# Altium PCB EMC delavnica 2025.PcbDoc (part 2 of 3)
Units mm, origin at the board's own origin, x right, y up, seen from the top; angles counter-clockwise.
Board outline 146.35 x 55.01 mm, 2 copper layers (Top Layer, Bottom Layer), stack 1.671 mm thick; 5 components, 5 nets, 32 pads, 0 vias.
Unrouted connection lines stored in the file: 7.
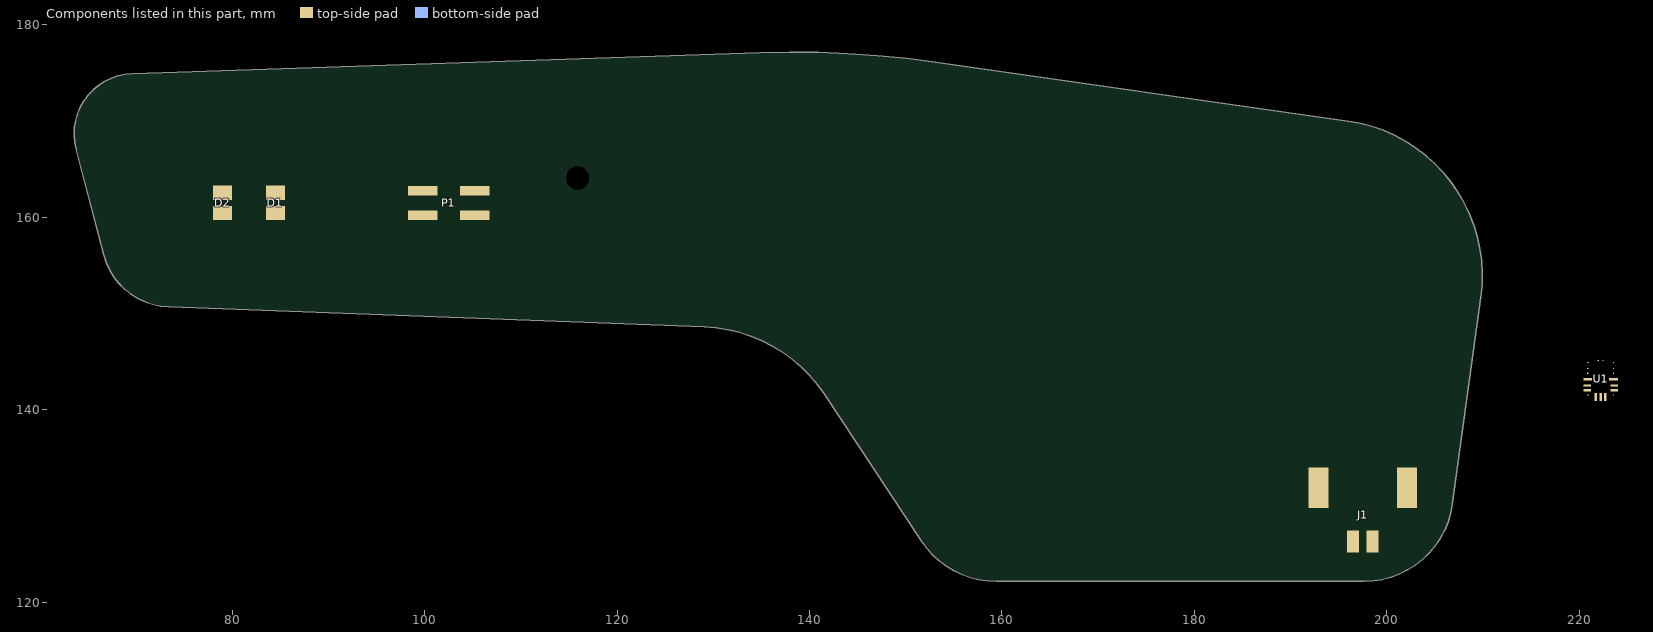
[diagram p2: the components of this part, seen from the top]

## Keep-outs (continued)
Top Layer: (continued)
  lines w0.203: 70.763,165.504 ccw(c71.252,166.272) 70.764,165.503 ; 74.51,166.422 cw(c73.659,166.748) 74.51,166.421 ; 121.556,166.282 121.788,166.242 ; 121.961,166.194 ccw(c121.633,165.344) 121.961,166.194 ; 122.178,166.11 cw(c121.852,165.259) 122.179,166.11 ; 123.096,162.363 ccw(c122.328,162.852) 123.097,162.364 ; 199.752,159.909 cw(c199.426,159.058) 199.753,159.909 ; 69.684,167.409 cw(c70.595,167.432) 69.697,167.587 ; 69.684,167.409 cw(c70.595,167.432) 69.697,167.587 ; 69.684,167.409 69.69,167.174 ; 69.69,167.174 ccw(c70.601,167.197) 69.712,166.996 ; 69.69,167.174 ccw(c70.601,167.197) 69.712,166.996 ; 69.697,167.587 69.737,167.818 ; 69.712,166.996 69.763,166.767 ; 69.737,167.818 cw(c70.635,167.663) 69.784,167.991 ; 69.737,167.818 cw(c70.635,167.663) 69.784,167.991 ; 69.763,166.767 ccw(c70.652,166.967) 69.819,166.598 ; 69.763,166.767 ccw(c70.652,166.967) 69.819,166.598 ; 69.784,167.991 ccw(c70.209,167.827) 69.784,167.991 ; 69.784,167.991 cw(c70.209,167.827) 69.784,167.991 ; 69.784,167.991 cw(c70.635,167.663) 69.785,167.991 ; 69.784,167.991 cw(c70.21,167.828) 69.784,167.991 ; 69.784,167.991 69.785,167.992 ; 69.784,167.991 cw(c70.209,167.827) 69.785,167.992 ; 69.785,167.991 cw(c70.635,167.663) 69.785,167.992 ; 69.785,167.991 69.868,168.209 ; 69.784,167.991 69.785,167.991 ; 69.785,167.992 ccw(c70.635,167.663) 69.785,167.992 ; 69.819,166.598 69.915,166.383 ; 69.868,168.209 ccw(c70.719,167.883) 69.868,168.209 ; 69.868,168.209 ccw(c70.719,167.883) 69.868,168.209 ; 69.868,168.209 cw(c70.719,167.883) 69.869,168.21 ; 69.868,168.209 cw(c70.294,168.046) 69.869,168.21 ; 69.868,168.209 ccw(c70.294,168.046) 69.868,168.209 ; 69.868,168.209 cw(c70.294,168.046) 69.869,168.21 ; 69.868,168.209 69.869,168.21 ; 69.869,168.21 cw(c70.719,167.883) 69.949,168.369 ; 69.869,168.21 cw(c70.719,167.883) 69.949,168.369 ; 69.869,168.21 ccw(c70.294,168.046) 69.869,168.21 ; 69.915,166.383 ccw(c70.748,166.752) 70.003,166.227 ; 69.915,166.383 ccw(c70.748,166.752) 70.003,166.227 ; 69.949,168.369 70.074,168.568 ; 70.003,166.227 ccw(c70.375,166.49) 70.003,166.227 ; 70.003,166.227 ccw(c70.375,166.49) 70.003,166.227 ; 70.003,166.227 ccw(c70.375,166.49) 70.003,166.227 ; 70.003,166.227 ccw(c70.375,166.49) 70.003,166.227 ; 70.003,166.227 ccw(c70.375,166.49) 70.003,166.227 cw(c70.748,166.752) 70.003,166.227 ; 70.003,166.227 ccw(c70.375,166.49) 70.003,166.227 ; 70.003,166.227 ccw(c70.748,166.752) 70.003,166.227 ; 70.003,166.227 70.138,166.036 ; 70.003,166.227 70.003,166.227 ; 70.074,168.568 cw(c70.845,168.082) 70.184,168.709 ; 70.074,168.568 cw(c70.845,168.082) 70.184,168.709 ; 70.138,166.036 ccw(c70.51,166.298) 70.138,166.036 ; 70.137,166.036 ccw(c70.51,166.298) 70.138,166.036 ; 70.138,166.036 ccw(c70.511,166.298) 70.138,166.036 ; 70.137,166.036 ccw(c70.511,166.298) 70.138,166.036 ; 70.137,166.036 70.138,166.036 ; 70.138,166.036 ccw(c70.51,166.298) 70.138,166.036 ; 70.138,166.036 ccw(c70.511,166.298) 70.138,166.035 ccw(c70.883,166.56) 70.255,165.9 ; 70.138,166.036 ccw(c70.511,166.298) 70.138,166.036 ; 70.138,166.036 ccw(c70.511,166.298) 70.138,166.036 ; 70.138,166.036 ccw(c70.883,166.56) 70.255,165.9 ; 70.138,166.036 ccw(c70.883,166.56) 70.138,166.036 ; 70.184,168.71 cw(c70.515,168.396) 70.185,168.711 ; 70.184,168.709 ccw(c70.514,168.395) 70.184,168.709 ; 70.184,168.71 ccw(c70.514,168.395) 70.184,168.709 ; 70.184,168.71 ccw(c70.845,168.082) 70.184,168.709 ; 70.184,168.71 cw(c70.845,168.082) 70.185,168.71 ; 70.184,168.709 ccw(c70.845,168.082) 70.184,168.709 ; 70.184,168.709 ccw(c70.515,168.396) 70.184,168.709 ; 70.184,168.71 ccw(c70.515,168.396) 70.184,168.709 ; 70.184,168.71 cw(c70.515,168.396) 70.185,168.71 70.185,168.71 ; 70.184,168.709 70.184,168.71 ; 70.185,168.711 ccw(c70.845,168.082) 70.185,168.71 ; 70.185,168.711 70.344,168.878 ; 70.185,168.71 70.185,168.711 ; 70.256,165.899 cw(c70.57,166.229) 70.255,165.9 ; 70.256,165.899 70.256,165.899 ; 70.256,165.899 70.255,165.9 ; 70.255,165.9 ccw(c70.569,166.23) 70.256,165.899 ; 70.255,165.9 ccw(c70.569,166.23) 70.255,165.9 ; 70.255,165.9 ccw(c70.569,166.23) 70.255,165.9 ; 70.255,165.9 ccw(c70.883,166.56) 70.256,165.899 ; 70.255,165.9 70.256,165.899 ; 70.256,165.899 ccw(c70.883,166.56) 70.256,165.899 ; 70.256,165.899 ccw(c70.883,166.56) 70.256,165.899 ; 70.256,165.899 70.424,165.739 ; 70.345,168.878 ccw(c71.006,168.252) 70.344,168.878 ; 70.345,168.878 cw(c71.006,168.252) 70.345,168.879 ; 70.344,168.878 cw(c70.675,168.565) 70.345,168.879 ; 70.345,168.878 70.345,168.879 cw(c70.675,168.565) 70.345,168.879 ; 70.344,168.878 70.345,168.878 ; 70.345,168.879 cw(c70.675,168.565) 70.346,168.88 ; 70.346,168.88 cw(c71.006,168.252) 70.346,168.88 ; 70.345,168.879 cw(c71.006,168.252) 70.346,168.88 ; 70.346,168.88 ccw(c70.676,168.566) 70.345,168.879 ; 70.345,168.879 70.346,168.88 ; 70.346,168.88 cw(c71.006,168.252) 70.481,168.996 ; 70.346,168.88 cw(c71.006,168.252) 70.481,168.996 ; 70.425,165.739 ccw(c70.739,166.068) 70.425,165.738 ; 70.424,165.739 ccw(c70.739,166.068) 70.425,165.739 ; 70.424,165.739 ccw(c70.738,166.069) 70.425,165.739 ; 70.424,165.739 cw(c70.738,166.069) 70.424,165.74 ccw(c71.053,166.398) 70.424,165.739 ; 70.425,165.739 ccw(c70.738,166.069) 70.425,165.738 ; 70.424,165.739 ccw(c70.738,166.069) 70.425,165.739 ; 70.425,165.739 ccw(c71.053,166.398) 70.425,165.738 ; 70.424,165.739 ccw(c71.053,166.398) 70.425,165.739 ; 70.425,165.739 70.425,165.738 ; 70.425,165.738 ccw(c71.053,166.398) 70.566,165.628 ; 70.425,165.738 ccw(c71.053,166.398) 70.425,165.738 ; 70.425,165.738 ccw(c71.053,166.398) 70.566,165.628 ; 70.481,168.996 70.673,169.132 ; 70.567,165.628 ccw(c70.81,166.013) 70.567,165.628 ; 70.566,165.628 ccw(c70.81,166.013) 70.567,165.628 ; 70.566,165.628 ccw(c70.81,166.013) 70.566,165.628 ; 70.567,165.628 ccw(c70.81,166.013) 70.567,165.628 ; 70.566,165.628 ccw(c70.81,166.013) 70.567,165.628 ; 70.566,165.628 ccw(c70.81,166.013) 70.566,165.628 ; 70.567,165.628 ccw(c70.81,166.013) 70.568,165.627 cw(c71.053,166.398) 70.567,165.628 ; 70.567,165.628 ccw(c70.81,166.013) 70.567,165.628 ; 70.567,165.628 ccw(c71.053,166.398) 70.567,165.628 ; 70.566,165.628 ccw(c71.053,166.398) 70.567,165.628 ; 70.566,165.628 ccw(c71.053,166.398) 70.566,165.628 ; 70.566,165.628 70.567,165.628 ; 70.567,165.628 70.764,165.503 ; 70.673,169.132 cw(c71.199,168.388) 70.828,169.22 ; 70.673,169.132 cw(c71.199,168.388) 70.828,169.22 ; 70.764,165.503 ccw(c71.008,165.887) 70.764,165.503 ; 70.764,165.503 ccw(c71.008,165.887) 70.764,165.503 ; 70.764,165.503 ccw(c71.007,165.888) 70.764,165.503 ; 70.764,165.503 ccw(c71.252,166.272) 70.764,165.503 ; 70.764,165.503 70.764,165.503 ; 70.764,165.503 ccw(c71.008,165.887) 70.765,165.503 ; 70.764,165.503 ccw(c71.008,165.887) 70.764,165.503 ; 70.764,165.503 ccw(c71.007,165.888) 70.764,165.503 ; 70.765,165.503 ccw(c71.252,166.272) 70.924,165.422 ; 70.764,165.503 ccw(c71.252,166.272) 70.924,165.422 ; 70.828,169.22 cw(c71.013,168.804) 70.829,169.22 ; 70.828,169.22 cw(c71.014,168.804) 70.829,169.22 ; 70.828,169.22 cw(c71.199,168.388) 70.829,169.22 ; 70.828,169.22 ccw(c71.199,168.388) 70.828,169.22 ; 70.828,169.22 70.829,169.22 ; 70.829,169.22 cw(c71.014,168.804) 70.829,169.221 ; 70.829,169.22 cw(c71.013,168.804) 70.829,169.221 ; 70.829,169.22 cw(c71.014,168.804) 70.829,169.221 ; 70.829,169.22 ccw(c71.199,168.388) 70.829,169.22 ; 70.829,169.22 cw(c71.199,168.388) 70.83,169.221 ccw(c71.014,168.804) 70.829,169.221 ; 70.829,169.22 70.829,169.221 ; 70.829,169.221 71.042,169.315 ; 70.924,165.422 71.143,165.338 ; 71.041,169.315 ccw(c71.413,168.483) 71.041,169.315 ; 71.041,169.315 cw(c71.413,168.483) 71.042,169.315 ; 71.042,169.315 ccw(c71.228,168.899) 71.041,169.315 ; 71.042,169.315 cw(c71.228,168.899) 71.042,169.315 ; 71.042,169.315 71.042,169.315 ; 71.041,169.315 71.042,169.315 ; 71.042,169.315 71.042,169.315 ; 71.042,169.315 71.042,169.315 ; 71.042,169.315 ccw(c71.227,168.899) 71.042,169.315 ; 71.043,169.316 cw(c71.413,168.483) 71.213,169.372 ; 71.042,169.315 cw(c71.413,168.483) 71.212,169.372 ; 71.043,169.316 ccw(c71.228,168.899) 71.042,169.315 ; 71.143,165.338 ccw(c71.471,166.188) 71.315,165.29 ; 71.143,165.338 ccw(c71.471,166.188) 71.315,165.29 ; 71.213,169.372 ccw(c71.313,168.928) 71.212,169.372 ; 71.213,169.372 ccw(c71.313,168.928) 71.213,169.372 ; 71.213,169.372 ccw(c71.313,168.928) 71.213,169.372 ; 71.213,169.372 cw(c71.313,168.928) 71.213,169.372 ; 71.213,169.372 cw(c71.413,168.483) 71.213,169.372 ; 71.213,169.372 ccw(c71.314,168.928) 71.213,169.372 ; 71.213,169.372 ccw(c71.314,168.928) 71.213,169.372 ; 71.213,169.372 71.214,169.372 ; 71.213,169.372 71.213,169.372 ; 71.213,169.372 71.213,169.372 ; 71.214,169.372 ccw(c71.314,168.928) 71.213,169.372 ; 71.214,169.372 ccw(c71.413,168.483) 71.213,169.372 ; 71.214,169.372 71.44,169.423 ; 71.315,165.29 ccw(c71.394,165.739) 71.315,165.29 ; 71.315,165.29 ccw(c71.471,166.188) 71.315,165.29 ; 71.315,165.29 ccw(c71.471,166.188) 71.315,165.29 ; 71.315,165.29 71.315,165.29 ; 71.315,165.29 ccw(c71.394,165.739) 71.316,165.29 ; 71.315,165.29 ccw(c71.393,165.739) 71.316,165.29 ; 71.315,165.29 ccw(c71.394,165.739) 71.317,165.29 ; 71.316,165.29 ccw(c71.471,166.188) 71.317,165.29 ; 71.315,165.29 ccw(c71.471,166.188) 71.316,165.29 ; 71.315,165.29 ccw(c71.471,166.188) 71.315,165.29 ; 71.316,165.29 71.317,165.29 ; 71.316,165.29 71.316,165.29 ; 71.317,165.29 ccw(c71.394,165.739) 71.317,165.29 ; 71.317,165.29 ccw(c71.394,165.739) 71.317,165.29 ; 71.317,165.29 71.546,165.25 ; 71.44,169.423 cw(c71.643,168.535) 71.441,169.424 ; 71.44,169.423 cw(c71.541,168.979) 71.441,169.424 ; 71.44,169.423 71.441,169.424 ; 71.44,169.423 71.44,169.423 ; 71.441,169.424 cw(c71.643,168.535) 71.442,169.424 ; 71.441,169.424 cw(c71.541,168.979) 71.441,169.424 ; 71.441,169.424 cw(c71.542,168.979) 71.441,169.424 ; 71.441,169.424 71.442,169.424 ; 71.441,169.424 71.441,169.424 ; 71.442,169.424 cw(c71.643,168.535) 71.619,169.446 ; 71.442,169.424 cw(c71.643,168.535) 71.619,169.446 ; 71.442,169.424 ccw(c71.541,168.979) 71.441,169.424 ; 71.442,169.424 ccw(c71.542,168.979) 71.441,169.424 ; 71.546,165.25 ccw(c71.703,166.148) 71.547,165.25 ; 71.546,165.25 ccw(c71.703,166.148) 71.546,165.25 ; 71.546,165.25 ccw(c71.625,165.699) 71.547,165.25 ; 71.546,165.25 ccw(c71.625,165.699) 71.546,165.25 ; 71.546,165.25 ccw(c71.624,165.699) 71.546,165.25 ; 71.546,165.25 ccw(c71.624,165.699) 71.546,165.25 ; 71.546,165.25 71.547,165.25 ; 71.546,165.25 71.546,165.25 ; 71.546,165.25 71.546,165.25 ; 71.546,165.25 ccw(c71.624,165.699) 71.547,165.25 ; 71.547,165.25 ccw(c71.703,166.148) 71.637,165.239 ; 71.547,165.25 ccw(c71.703,166.148) 71.637,165.239 ; 71.547,165.25 ccw(c71.625,165.699) 71.547,165.25 ; 71.619,169.446 cw(c71.643,168.535) 71.62,169.446 ; 71.619,169.446 ccw(c71.631,168.99) 71.619,169.446 ; 71.619,169.446 cw(c71.631,168.99) 71.62,169.446 ; 71.62,169.446 ccw(c71.631,168.991) 71.619,169.446 ; 71.62,169.446 71.62,169.446 ; 71.62,169.446 71.62,169.446 ; 71.62,169.446 71.62,169.446 ; 71.619,169.446 71.62,169.446 ; 71.62,169.446 ccw(c71.631,168.991) 71.62,169.446 ; 71.62,169.446 ccw(c71.643,168.535) 71.62,169.446 ; 71.62,169.446 ccw(c71.631,168.99) 71.62,169.446 ; 71.62,169.446 71.852,169.452 ; 71.62,169.446 71.62,169.446 ; 71.637,165.239 72.434,165.181 ; 71.853,169.452 ccw(c71.878,168.541) 71.852,169.452 cw(c71.865,168.997) 71.852,169.452 ; 71.853,169.452 cw(c71.878,168.541) 71.853,169.452 ; 71.853,169.452 cw(c71.865,168.997) 71.853,169.452 ; 71.853,169.452 cw(c71.866,168.997) 71.853,169.452 ; 71.852,169.452 cw(c71.865,168.997) 71.853,169.452 ; 71.853,169.452 71.853,169.452 ; 71.852,169.452 71.853,169.452 ; 71.854,169.452 ccw(c71.878,168.541) 71.854,169.452 ; 71.854,169.452 cw(c71.878,168.541) 71.944,169.45 ; 71.854,169.452 ccw(c71.878,168.541) 71.853,169.452 ; 71.854,169.452 cw(c71.878,168.541) 71.944,169.45 ; 71.854,169.452 ccw(c71.865,168.997) 71.853,169.452 ; 71.854,169.452 ccw(c71.866,168.997) 71.853,169.452 ; 71.853,169.452 71.854,169.452 ; 71.944,169.45 72.742,169.392 ; 72.434,165.181 ccw(c72.501,166.089) 72.525,165.178 ; 72.434,165.181 ccw(c72.501,166.089) 72.525,165.178 ; 72.525,165.178 ccw(c72.513,165.634) 72.526,165.178 ; 72.525,165.178 ccw(c72.513,165.634) 72.525,165.178 ; 72.525,165.178 ccw(c72.501,166.089) 72.526,165.178 ; 72.525,165.178 ccw(c72.514,165.634) 72.526,165.178 ; 72.525,165.178 ccw(c72.514,165.634) 72.525,165.178 ; 72.525,165.178 72.526,165.178 ; 72.526,165.178 ccw(c72.514,165.634) 72.527,165.179 ; 72.526,165.178 ccw(c72.501,166.089) 72.527,165.179 ; 72.526,165.178 72.527,165.179 ; 72.526,165.178 72.526,165.178 ; 72.527,165.179 72.758,165.185 ; 72.527,165.179 72.527,165.179 ; 72.742,169.392 cw(c72.676,168.483) 72.831,169.381 ; 72.742,169.392 cw(c72.676,168.483) 72.831,169.381 ; 72.758,165.185 ccw(c72.736,166.095) 72.759,165.185 ; 72.758,165.185 ccw(c72.736,166.095) 72.758,165.185 ; 72.758,165.185 ccw(c72.747,165.64) 72.759,165.185 ; 72.758,165.185 72.759,165.185 ; 72.758,165.185 72.758,165.185 ; 72.759,165.185 ccw(c72.748,165.64) 72.759,165.185 ; 72.759,165.185 ccw(c72.747,165.64) 72.759,165.185 ; 72.759,165.185 ccw(c72.747,165.64) 72.759,165.185 ; 72.759,165.185 ccw(c72.736,166.095) 72.76,165.185 ; 72.759,165.185 72.76,165.185 ; 72.759,165.185 72.759,165.185 ; 72.759,165.185 ccw(c72.748,165.64) 72.76,165.185 ; 72.759,165.185 ccw(c72.747,165.64) 72.76,165.185 ; 72.76,165.185 ccw(c72.736,166.095) 72.937,165.207 ; 72.76,165.185 ccw(c72.736,166.095) 72.937,165.207 ; 72.76,165.185 ccw(c72.736,166.095) 72.76,165.185 ; 72.831,169.381 73.063,169.34 ; 72.937,165.207 73.166,165.259 ; 73.063,169.34 cw(c72.907,168.443) 73.235,169.293 ; 73.063,169.34 cw(c72.907,168.443) 73.235,169.293 ; 73.166,165.259 ccw(c72.965,166.147) 73.335,165.315 ; 73.166,165.259 ccw(c72.965,166.147) 73.335,165.315 ; 73.235,169.293 cw(c72.907,168.443) 73.236,169.293 ; 73.235,169.293 ccw(c72.907,168.443) 73.235,169.293 ; 73.235,169.293 cw(c73.071,168.868) 73.236,169.293 ; 73.235,169.293 cw(c73.072,168.867) 73.236,169.293 ; 73.235,169.293 73.236,169.293 ; 73.236,169.293 cw(c72.907,168.443) 73.237,169.292 ; 73.236,169.293 cw(c73.072,168.867) 73.237,169.292 ; 73.236,169.292 ccw(c73.072,168.867) 73.236,169.293 ; 73.236,169.292 73.237,169.292 ; 73.237,169.292 ccw(c72.907,168.443) 73.237,169.292 ; 73.237,169.292 ccw(c73.072,168.867) 73.237,169.292 ; 73.237,169.292 73.453,169.209 ; 73.237,169.292 73.237,169.292 ; 73.335,165.315 ccw(c73.151,165.731) 73.336,165.315 ; 73.335,165.315 ccw(c72.965,166.147) 73.336,165.315 ; 73.335,165.315 ccw(c72.965,166.147) 73.336,165.315 ; 73.335,165.315 73.336,165.315 ; 73.336,165.315 ccw(c73.151,165.731) 73.336,165.315 ; 73.336,165.315 ccw(c73.151,165.731) 73.337,165.315 cw(c72.965,166.147) 73.336,165.315 ; 73.336,165.315 ccw(c73.151,165.731) 73.336,165.315 ; 73.336,165.315 ccw(c73.15,165.731) 73.336,165.315 ; 73.336,165.315 ccw(c72.965,166.147) 73.336,165.315 ; 73.336,165.315 73.55,165.41 ; 73.453,169.209 ccw(c73.126,168.358) 73.452,169.209 ; 73.453,169.209 ccw(c73.126,168.358) 73.453,169.209 ; 73.453,169.209 cw(c73.126,168.358) 73.454,169.208 ; 73.453,169.209 cw(c73.289,168.784) 73.454,169.208 ; 73.453,169.209 ccw(c73.289,168.784) 73.453,169.209 ; 73.453,169.209 cw(c73.29,168.783) 73.454,169.208 ; 73.453,169.209 73.453,169.209 ; 73.453,169.209 73.453,169.209 ; 73.453,169.209 73.454,169.208 ; 73.454,169.208 cw(c73.126,168.358) 73.614,169.128 ; 73.454,169.208 cw(c73.126,168.358) 73.614,169.128 ; 73.454,169.208 ccw(c73.29,168.783) 73.454,169.208 ; 73.55,165.41 ccw(c73.365,165.826) 73.551,165.411 ; 73.55,165.41 ccw(c73.365,165.826) 73.55,165.41 ; 73.55,165.41 ccw(c73.365,165.827) 73.55,165.41 ; 73.55,165.41 ccw(c73.365,165.827) 73.55,165.41 ; 73.55,165.41 ccw(c73.365,165.826) 73.55,165.41 ; 73.549,165.41 ccw(c73.365,165.826) 73.55,165.41 ; 73.55,165.41 ccw(c73.18,166.243) 73.551,165.411 ; 73.55,165.41 ccw(c73.18,166.243) 73.55,165.41 ; 73.549,165.41 ccw(c73.18,166.243) 73.55,165.41 ; 73.55,165.41 73.551,165.411 ; 73.551,165.411 ccw(c73.18,166.243) 73.706,165.499 ; 73.55,165.41 ccw(c73.18,166.243) 73.551,165.411 ; 73.551,165.411 ccw(c73.18,166.243) 73.706,165.499 ; 73.614,169.128 73.813,169.002 ; 73.706,165.499 73.898,165.634 ; 73.813,169.002 cw(c73.325,168.232) 73.953,168.892 ; 73.813,169.002 cw(c73.325,168.232) 73.953,168.892 ; 73.898,165.634 ccw(c73.372,166.379) 74.032,165.751 ; 73.898,165.634 ccw(c73.372,166.379) 74.032,165.751 ; 73.953,168.892 74.124,168.73 ; 74.032,165.751 ccw(c73.372,166.379) 74.033,165.752 ; 74.032,165.751 ccw(c73.372,166.379) 74.033,165.751 ccw(c73.702,166.065) 74.033,165.752 ; 74.032,165.751 ccw(c73.703,166.066) 74.033,165.752 ; 74.032,165.751 74.033,165.752 ; 74.033,165.752 ccw(c73.703,166.066) 74.034,165.753 ; 74.033,165.752 ccw(c73.372,166.379) 74.034,165.752 ; 74.033,165.752 ccw(c73.703,166.066) 74.033,165.752 ; 74.033,165.752 74.034,165.752 ; 74.034,165.752 ccw(c73.372,166.379) 74.034,165.753 ; 74.034,165.752 74.034,165.753 ; 74.034,165.753 74.193,165.92 ; 74.124,168.73 cw(c73.495,168.07) 74.24,168.595 ; 74.124,168.73 cw(c73.495,168.07) 74.24,168.595 ; 74.194,165.921 ccw(c73.863,166.234) 74.194,165.921 ; 74.193,165.92 ccw(c73.534,166.549) 74.194,165.921 ; 74.193,165.92 ccw(c73.534,166.549) 74.193,165.92 ; 74.193,165.92 ccw(c73.863,166.234) 74.194,165.921 ; 74.193,165.92 74.194,165.921 ; 74.193,165.92 74.193,165.92 ; 74.194,165.921 ccw(c73.863,166.234) 74.194,165.921 ; 74.194,165.921 ccw(c73.534,166.549) 74.195,165.922 ; 74.194,165.921 ccw(c73.864,166.235) 74.194,165.921 ; 74.194,165.921 74.195,165.922 ; 74.195,165.922 ccw(c73.534,166.549) 74.304,166.062 ; 74.195,165.921 ccw(c73.534,166.549) 74.195,165.922 ; 74.194,165.921 ccw(c73.863,166.234) 74.195,165.922 ; 74.195,165.922 ccw(c73.534,166.549) 74.304,166.062 ; 74.194,165.921 ccw(c73.864,166.235) 74.195,165.921 ; 74.241,168.594 ccw(c73.495,168.07) 74.241,168.595 ; 74.241,168.594 ccw(c73.495,168.07) 74.241,168.594 ; 74.241,168.594 ccw(c73.868,168.332) 74.241,168.595 ; 74.241,168.594 74.241,168.595 ; 74.241,168.594 74.241,168.594 ; 74.241,168.594 74.375,168.404 ; 74.24,168.595 ccw(c73.495,168.07) 74.24,168.595 ; 74.241,168.595 ccw(c73.495,168.07) 74.24,168.595 ; 74.241,168.595 ccw(c73.868,168.333) 74.24,168.595 ; 74.241,168.595 ccw(c73.868,168.332) 74.24,168.595 ; 74.241,168.595 ccw(c73.868,168.332) 74.241,168.595 ; 74.24,168.595 74.241,168.595 ; 74.241,168.595 74.241,168.595 ; 74.304,166.062 74.43,166.261 ; 74.376,168.403 ccw(c74.003,168.141) 74.375,168.404 ; 74.376,168.403 cw(c74.003,168.141) 74.376,168.403 ; 74.375,168.403 ccw(c73.631,167.878) 74.375,168.404 ; 74.376,168.403 ccw(c73.631,167.878) 74.375,168.403 ; 74.376,168.403 cw(c73.631,167.878) 74.376,168.403 ; 74.376,168.403 ccw(c74.003,168.141) 74.375,168.404 ; 74.376,168.403 cw(c74.003,168.141) 74.376,168.403 ; 74.376,168.403 ccw(c74.003,168.141) 74.375,168.404 ; 74.376,168.403 74.376,168.403 ; 74.375,168.404 74.375,168.404 ; 74.375,168.404 74.375,168.403 ; 74.376,168.403 cw(c73.631,167.878) 74.464,168.248 ; 74.376,168.403 ccw(c73.631,167.878) 74.376,168.403 ; 74.376,168.403 cw(c73.631,167.878) 74.464,168.248 ; 74.43,166.261 ccw(c73.659,166.748) 74.51,166.421 ; 74.43,166.261 ccw(c73.659,166.748) 74.51,166.421 ; 74.464,168.248 74.559,168.033 ; 74.51,166.421 ccw(c74.085,166.585) 74.51,166.421 ; 74.51,166.421 ccw(c74.085,166.584) 74.51,166.421 ; 74.51,166.421 ccw(c74.085,166.584) 74.51,166.421 ; 74.51,166.421 ccw(c74.085,166.584) 74.51,166.421 ; 74.51,166.421 ccw(c73.659,166.748) 74.51,166.421 ; 74.51,166.421 ccw(c73.659,166.748) 74.51,166.421 ; 74.51,166.421 74.594,166.639 ; 74.51,166.421 74.51,166.421 ; 74.559,168.033 cw(c73.726,167.663) 74.615,167.863 ; 74.559,168.033 cw(c73.726,167.663) 74.615,167.863 ; 74.594,166.64 ccw(c73.744,166.967) 74.642,166.812 ; 74.594,166.639 ccw(c73.744,166.967) 74.594,166.64 ; 74.594,166.639 ccw(c73.744,166.967) 74.594,166.639 ; 74.594,166.639 ccw(c73.744,166.967) 74.594,166.639 ; 74.594,166.639 ccw(c74.169,166.803) 74.594,166.64 ; 74.594,166.64 ccw(c74.169,166.804) 74.594,166.64 ccw(c73.744,166.967) 74.642,166.812 ; 74.594,166.639 ccw(c74.169,166.804) 74.594,166.64 ; 74.594,166.639 ccw(c74.169,166.804) 74.594,166.639 ; 74.594,166.639 74.594,166.64 ; 74.594,166.639 74.594,166.639 ; 74.615,167.863 74.667,167.634 ; 74.642,166.812 74.682,167.044 ; 74.667,167.634 cw(c73.778,167.434) 74.689,167.457 ; 74.667,167.634 cw(c73.778,167.434) 74.689,167.457 ; 74.682,167.044 ccw(c73.784,167.199) 74.695,167.199 ; 74.682,167.044 ccw(c73.784,167.199) 74.695,167.199 ; 74.689,167.457 74.695,167.222 ; 74.695,167.199 ccw(c73.784,167.199) 74.695,167.222 ; 74.695,167.199 ccw(c73.784,167.199) 74.695,167.222 ; 119.148,163.453 ccw(c119.603,163.465) 119.148,163.452 ; 119.148,163.452 ccw(c119.603,163.465) 119.148,163.452 cw(c120.059,163.478) 119.148,163.453 ; 119.148,163.453 cw(c119.603,163.466) 119.148,163.454 ; 119.148,163.453 ccw(c119.603,163.466) 119.148,163.453 ; 119.148,163.453 cw(c119.603,163.465) 119.148,163.454 ; 119.148,163.453 ccw(c119.603,163.465) 119.148,163.453 ; 119.148,163.453 cw(c120.059,163.478) 119.148,163.454 ; 119.148,163.453 ccw(c120.059,163.478) 119.148,163.453 ; 119.148,163.452 119.154,163.22 ; 119.148,163.453 119.148,163.452 ; 119.148,163.453 119.148,163.453 ; 119.148,163.453 119.148,163.454 ; 119.148,163.454 cw(c120.059,163.478) 119.15,163.544 ; 119.148,163.454 cw(c120.059,163.478) 119.15,163.544 ; 119.148,163.454 ccw(c120.059,163.478) 119.148,163.454 ; 119.15,163.544 119.208,164.342 ; 119.154,163.22 ccw(c119.609,163.231) 119.154,163.219 ; 119.154,163.219 cw(c119.61,163.231) 119.154,163.22 ; 119.154,163.219 ccw(c119.61,163.231) 119.154,163.219 ; 119.154,163.219 ccw(c120.065,163.243) 119.176,163.042 ; 119.154,163.219 cw(c120.065,163.243) 119.154,163.22 ; 119.154,163.219 ccw(c120.065,163.243) 119.176,163.042 ; 119.154,163.22 119.154,163.219 ; 119.154,163.22 119.154,163.22 ; 119.154,163.22 119.154,163.22 ; 119.154,163.22 119.154,163.22 ; 119.154,163.22 ccw(c119.61,163.231) 119.154,163.22 ; 119.154,163.22 ccw(c120.065,163.243) 119.154,163.22 ; 119.154,163.22 ccw(c119.609,163.231) 119.154,163.22 ; 119.154,163.22 119.154,163.22 ; 119.177,163.04 cw(c119.621,163.141) 119.176,163.041 ; 119.177,163.04 cw(c120.065,163.243) 119.176,163.041 ; 119.177,163.04 119.228,162.814 ; 119.177,163.04 119.177,163.04 ; 119.177,163.04 119.176,163.041 ; 119.176,163.042 ccw(c119.621,163.142) 119.176,163.041 ; 119.176,163.041 ccw(c119.621,163.142) 119.176,163.041 ; 119.176,163.042 ccw(c119.621,163.141) 119.176,163.041 ; 119.176,163.041 ccw(c119.621,163.141) 119.176,163.041 ; 119.176,163.042 ccw(c120.065,163.243) 119.176,163.041 ; 119.176,163.041 119.176,163.041 ; 119.176,163.042 119.176,163.041 ; 119.208,164.342 cw(c120.117,164.276) 119.219,164.431 ; 119.208,164.342 cw(c120.117,164.276) 119.219,164.431 ; 119.219,164.431 119.26,164.663 ; 119.228,162.813 ccw(c119.672,162.914) 119.228,162.813 ; 119.228,162.813 ccw(c119.672,162.914) 119.228,162.813 ; 119.228,162.812 ccw(c120.117,163.013) 119.285,162.642 ; 119.228,162.813 cw(c120.117,163.013) 119.228,162.813 ; 119.228,162.813 ccw(c120.117,163.013) 119.284,162.643 ; 119.228,162.813 cw(c119.672,162.913) 119.228,162.813 ; 119.228,162.813 ccw(c119.672,162.913) 119.228,162.813 ; 119.228,162.813 ccw(c119.672,162.913) 119.228,162.813 ; 119.228,162.813 ccw(c119.672,162.913) 119.228,162.812 ; 119.228,162.813 119.228,162.813 ; 119.228,162.813 119.228,162.813 ; 119.228,162.813 119.228,162.814 ; 119.228,162.814 ccw(c120.117,163.013) 119.228,162.813 ; 119.228,162.814 ccw(c119.672,162.914) 119.228,162.813 ; 119.26,164.663 cw(c120.157,164.507) 119.307,164.835 ; 119.26,164.663 cw(c120.157,164.507) 119.307,164.835 ; 119.285,162.642 cw(c119.701,162.828) 119.285,162.642 ; 119.285,162.642 ccw(c119.701,162.828) 119.285,162.641 ; 119.285,162.641 cw(c120.117,163.013) 119.285,162.642 ; 119.285,162.641 ccw(c120.117,163.013) 119.285,162.641 ; 119.285,162.642 119.379,162.429 ; 119.285,162.642 119.285,162.642 ; 119.285,162.642 119.285,162.642 ; 119.285,162.642 119.285,162.641 ; 119.285,162.642 119.285,162.642 ; 119.284,162.643 ccw(c119.701,162.828) 119.285,162.642 ; 119.285,162.642 ccw(c119.701,162.827) 119.285,162.642 ; 119.307,164.835 cw(c119.733,164.672) 119.307,164.836 ; 119.307,164.835 cw(c119.732,164.671) 119.307,164.836 ; 119.307,164.835 ccw(c120.157,164.507) 119.307,164.835 ; 119.307,164.835 cw(c120.157,164.507) 119.307,164.836 ; 119.307,164.835 119.307,164.836 ; 119.308,164.836 ccw(c119.733,164.672) 119.307,164.836 ; 119.307,164.836 cw(c119.733,164.672) 119.308,164.837 ; 119.307,164.836 cw(c120.157,164.507) 119.308,164.837 ; 119.308,164.836 119.308,164.837 ; 119.308,164.837 ccw(c119.733,164.672) 119.308,164.837 ; 119.308,164.837 ccw(c120.157,164.507) 119.308,164.837 ; 119.308,164.837 119.308,164.837 ; 119.308,164.837 119.391,165.053 ; 119.38,162.428 ccw(c120.212,162.799) 119.38,162.428 ; 119.38,162.428 ccw(c120.212,162.799) 119.468,162.273 ; 119.38,162.428 cw(c120.212,162.799) 119.38,162.429 ; 119.38,162.428 ccw(c120.212,162.799) 119.468,162.273 ; 119.38,162.428 cw(c119.796,162.614) 119.38,162.429 ; 119.38,162.428 cw(c119.796,162.613) 119.38,162.429 ; 119.38,162.428 119.38,162.429 ; 119.38,162.429 cw(c120.212,162.799) 119.379,162.43 ccw(c119.796,162.614) 119.379,162.429 ; 119.38,162.429 ccw(c120.212,162.799) 119.38,162.429 ; 119.379,162.429 ccw(c119.796,162.614) 119.38,162.429 ; 119.379,162.429 ccw(c119.796,162.613) 119.38,162.429 ; 119.379,162.429 ccw(c119.796,162.614) 119.38,162.429 ; 119.379,162.429 119.38,162.429 ; 119.391,165.053 cw(c119.817,164.89) 119.392,165.054 ; 119.391,165.053 ccw(c119.816,164.889) 119.391,165.053 ; 119.391,165.053 cw(c119.816,164.889) 119.392,165.054 ; 119.391,165.053 cw(c120.242,164.726) 119.392,165.054 ; 119.391,165.053 ccw(c120.242,164.726) 119.391,165.053 ; 119.391,165.053 ccw(c120.242,164.726) 119.391,165.052 ; 119.391,165.053 119.392,165.054 ; 119.391,165.053 119.391,165.053 ; 119.391,165.053 119.391,165.053 ; 119.392,165.054 ccw(c119.817,164.89) 119.392,165.054 ; 119.392,165.054 cw(c120.242,164.726) 119.472,165.214 ; 119.392,165.054 cw(c120.242,164.726) 119.472,165.214 ; 119.468,162.273 119.604,162.081 ; 119.472,165.214 119.598,165.413 ; 119.598,165.413 cw(c120.368,164.925) 119.708,165.553 ; 119.598,165.413 cw(c120.368,164.925) 119.708,165.553 ; 119.604,162.081 ccw(c120.348,162.606) 119.72,161.946 ; 119.604,162.081 ccw(c120.348,162.606) 119.72,161.946 ; 119.708,165.553 119.87,165.724 ; 119.72,161.946 ccw(c120.348,162.606) 119.721,161.945 ; 119.72,161.946 ccw(c120.348,162.606) 119.72,161.946 ccw(c120.034,162.276) 119.721,161.945 ; 119.72,161.946 ccw(c120.035,162.275) 119.721,161.945 ; 119.72,161.946 119.721,161.945 ; 119.722,161.944 cw(c120.035,162.275) 119.721,161.945 ; 119.722,161.945 cw(c120.348,162.606) 119.721,161.945 ; 119.722,161.945 ccw(c120.348,162.606) 119.722,161.944 ; 119.722,161.944 119.889,161.785 ; 119.722,161.945 119.722,161.944 ; 119.722,161.945 119.721,161.945 ; 119.721,161.945 ccw(c120.035,162.275) 119.721,161.945 ; 119.87,165.724 cw(c120.53,165.095) 120.005,165.84 ; 119.87,165.724 cw(c120.53,165.095) 120.005,165.84 ; 119.889,161.785 ccw(c120.518,162.445) 119.89,161.785 ; 119.89,161.785 ccw(c120.518,162.445) 119.89,161.784 ; 119.889,161.785 ccw(c120.204,162.115) 119.89,161.784 ; 119.89,161.785 119.89,161.785 ; 119.889,161.785 119.89,161.785 ; 119.89,161.785 ccw(c120.204,162.115) 119.89,161.784 ; 119.89,161.784 ccw(c120.204,162.115) 119.891,161.784 ; 119.891,161.784 ccw(c120.204,162.115) 119.891,161.784 ; 119.891,161.784 ccw(c120.518,162.445) 119.891,161.784 ; 119.89,161.784 ccw(c120.518,162.445) 119.891,161.784 ; 119.89,161.784 ccw(c120.205,162.114) 119.891,161.784 ; 119.891,161.784 ccw(c120.205,162.114) 119.891,161.784 ; 119.89,161.784 119.891,161.784 ; 119.891,161.784 ccw(c120.518,162.445) 120.032,161.674 ; 119.891,161.784 ccw(c120.518,162.445) 120.032,161.674 ; 120.005,165.841 ccw(c120.268,165.468) 120.005,165.841 ; 120.005,165.841 ccw(c120.268,165.468) 120.005,165.84 ; 120.005,165.841 cw(c120.268,165.468) 120.006,165.841 ; 120.005,165.841 ccw(c120.267,165.468) 120.005,165.84 ; 120.005,165.841 cw(c120.53,165.095) 120.006,165.841 ; 120.005,165.841 ccw(c120.53,165.095) 120.005,165.84 ; 120.005,165.84 ccw(c120.53,165.095) 120.005,165.84 ; 120.005,165.841 120.006,165.841 ; 120.005,165.841 120.005,165.841 ; 120.005,165.84 120.005,165.841 ; 120.006,165.841 ccw(c120.53,165.095) 120.006,165.841 ; 120.006,165.841 120.196,165.975 ; 120.006,165.841 120.006,165.841 ; 120.032,161.674 120.231,161.549 ; 120.197,165.976 ccw(c120.459,165.603) 120.196,165.975 ; 120.197,165.976 cw(c120.459,165.603) 120.197,165.976 cw(c120.722,165.231) 120.197,165.976 ; 120.197,165.976 ccw(c120.459,165.603) 120.196,165.975 ; 120.197,165.976 cw(c120.722,165.231) 120.197,165.976 ; 120.197,165.976 ccw(c120.722,165.231) 120.197,165.975 ; 120.197,165.975 ccw(c120.722,165.231) 120.196,165.975 ; 120.197,165.976 cw(c120.459,165.603) 120.197,165.976 ; 120.197,165.976 ccw(c120.459,165.603) 120.196,165.975 ; 120.196,165.975 120.197,165.975 ; 120.196,165.975 120.196,165.975 ; 120.197,165.976 120.197,165.976 ; 120.197,165.976 cw(c120.722,165.231) 120.352,166.064 ; 120.197,165.976 cw(c120.722,165.231) 120.352,166.064 ; 120.231,161.549 ccw(c120.717,162.319) 120.39,161.469 ; 120.231,161.549 ccw(c120.717,162.319) 120.39,161.469 ; 120.352,166.064 120.567,166.159 ; 120.39,161.469 ccw(c120.554,161.894) 120.39,161.469 ; 120.39,161.469 ccw(c120.554,161.894) 120.391,161.468 ; 120.39,161.469 ccw(c120.554,161.894) 120.391,161.468 ; 120.39,161.469 ccw(c120.717,162.319) 120.391,161.468 ; 120.39,161.469 120.391,161.468 ; 120.391,161.468 ccw(c120.554,161.894) 120.391,161.468 ; 120.391,161.468 ccw(c120.717,162.319) 120.391,161.468 ; 120.391,161.468 ccw(c120.717,162.319) 120.391,161.468 ; 120.391,161.468 120.609,161.385 ; 120.567,166.159 cw(c120.937,165.326) 120.737,166.215 ; 120.567,166.159 cw(c120.937,165.326) 120.737,166.215 ; 120.609,161.385 cw(c120.937,162.235) 120.608,161.385 ; 120.609,161.385 ccw(c120.937,162.235) 120.609,161.384 ; 120.609,161.385 120.609,161.384 ; 120.608,161.385 ccw(c120.937,162.235) 120.608,161.385 ; 120.608,161.385 ccw(c120.773,161.809) 120.609,161.384 ; 120.608,161.385 120.609,161.384 ; 120.609,161.384 ccw(c120.772,161.81) 120.609,161.384 ; 120.609,161.384 ccw(c120.937,162.235) 120.782,161.337 ; 120.609,161.384 ccw(c120.937,162.235) 120.782,161.337 ; 120.609,161.384 ccw(c120.773,161.809) 120.609,161.384 ; 120.609,161.384 ccw(c120.773,161.809) 120.609,161.384 ; 120.737,166.215 120.966,166.267 ; 120.782,161.337 121.013,161.297 ; 120.966,166.267 cw(c121.166,165.378) 121.143,166.289 ; 120.966,166.267 cw(c121.166,165.378) 121.143,166.289 ; 121.013,161.297 ccw(c121.168,162.195) 121.191,161.284 ; 121.013,161.297 ccw(c121.168,162.195) 121.191,161.284 ; 121.143,166.289 121.378,166.295 ; 121.191,161.284 121.426,161.29 ; 121.378,166.295 cw(c121.401,165.384) 121.401,166.295 ; 121.378,166.295 cw(c121.401,165.384) 121.401,166.295 ; 121.401,166.295 cw(c121.401,165.384) 121.556,166.282 ccw(c121.401,165.384) 121.401,166.295 ; 121.426,161.29 ccw(c121.403,162.201) 121.604,161.312 ; 121.426,161.29 ccw(c121.403,162.201) 121.604,161.312 ; 121.604,161.312 121.833,161.363 ; 121.788,166.242 cw(c121.633,165.344) 121.96,166.194 cw(c121.796,165.769) 121.961,166.194 ; 121.788,166.242 cw(c121.633,165.344) 121.961,166.194 ; 121.833,161.363 ccw(c121.633,162.252) 122.002,161.419 ; 121.833,161.363 ccw(c121.633,162.252) 122.002,161.419 ; 121.961,166.194 ccw(c121.796,165.769) 121.961,166.194 ; 121.961,166.194 ccw(c121.796,165.769) 121.961,166.194 ; 121.961,166.194 ccw(c121.797,165.769) 121.961,166.194 ; 121.961,166.194 ccw(c121.633,165.344) 121.961,166.194 ; 121.961,166.194 ccw(c121.633,165.344) 121.961,166.194 ; 121.961,166.194 122.179,166.11 ; 121.961,166.194 121.961,166.194 ; 121.961,166.194 121.961,166.194 ; 122.002,161.419 122.217,161.515 ; 122.179,166.11 cw(c121.852,165.259) 122.339,166.03 ; 122.179,166.11 cw(c121.852,165.259) 122.339,166.03 ; 122.179,166.11 ccw(c121.852,165.259) 122.179,166.11 ; 122.179,166.11 ccw(c121.852,165.259) 122.179,166.11 ; 122.179,166.11 ccw(c122.016,165.685) 122.179,166.11 ; 122.179,166.11 ccw(c122.016,165.685) 122.179,166.11 ; 122.179,166.11 ccw(c122.016,165.685) 122.179,166.11 ; 122.179,166.11 ccw(c122.015,165.685) 122.179,166.11 ; 122.179,166.11 122.179,166.11 ; 122.217,161.515 ccw(c121.848,162.348) 122.373,161.603 ; 122.217,161.515 ccw(c121.848,162.348) 122.373,161.603 ; 122.339,166.03 122.538,165.904 ; 122.373,161.603 ccw(c121.848,162.348) 122.373,161.603 ; 122.373,161.603 ccw(c122.11,161.975) 122.373,161.603 ; 122.373,161.603 ccw(c122.11,161.975) 122.373,161.603 ; 122.373,161.603 122.373,161.603 ; 122.373,161.603 ccw(c121.848,162.348) 122.373,161.603 cw(c122.11,161.975) 122.373,161.603 ; 122.373,161.603 ccw(c122.11,161.975) 122.373,161.603 ; 122.373,161.603 ccw(c122.11,161.975) 122.373,161.603 ; 122.373,161.603 ccw(c122.11,161.975) 122.373,161.603 ; 122.373,161.603 122.564,161.738 ; 122.538,165.904 cw(c122.051,165.134) 122.678,165.795 ; 122.538,165.904 cw(c122.051,165.134) 122.678,165.795 ; 122.564,161.737 ccw(c122.302,162.111) 122.564,161.738 ; 122.564,161.738 ccw(c122.302,162.111) 122.564,161.738 ; 122.564,161.737 ccw(c122.302,162.11) 122.564,161.738 ; 122.564,161.738 ccw(c122.302,162.11) 122.564,161.738 ; 122.564,161.737 122.564,161.738 ; 122.564,161.738 ccw(c122.04,162.483) 122.564,161.738 ; 122.564,161.738 ccw(c122.04,162.483) 122.7,161.855 ; 122.564,161.738 ccw(c122.302,162.111) 122.564,161.738 ; 122.564,161.738 ccw(c122.302,162.111) 122.564,161.738 ; 122.564,161.738 ccw(c122.302,162.111) 122.565,161.738 ccw(c122.04,162.483) 122.7,161.855 ; 122.564,161.738 ccw(c122.302,162.11) 122.564,161.738 ; 122.679,165.794 cw(c122.365,165.464) 122.679,165.794 ; 122.679,165.794 ccw(c122.365,165.464) 122.679,165.795 ; 122.678,165.795 cw(c122.051,165.134) 122.679,165.794 ; 122.679,165.794 cw(c122.366,165.463) 122.679,165.794 ; 122.679,165.794 ccw(c122.366,165.463) 122.678,165.795 ; 122.679,165.795 ccw(c122.051,165.134) 122.678,165.795 ; 122.678,165.795 122.679,165.794 ; 122.68,165.793 ccw(c122.366,165.463) 122.679,165.794 ; 122.68,165.793 ccw(c122.051,165.134) 122.68,165.793 ; 122.68,165.793 ccw(c122.051,165.134) 122.679,165.794 ; 122.679,165.794 ccw(c122.366,165.463) 122.679,165.794 ; 122.68,165.793 122.847,165.634 ; 122.68,165.793 122.68,165.793 ; 122.679,165.794 122.68,165.793 ; 122.7,161.855 ccw(c122.04,162.483) 122.701,161.856 ; 122.7,161.855 ccw(c122.371,162.17) 122.701,161.856 ; 122.7,161.855 ccw(c122.37,162.169) 122.7,161.855 ; 122.7,161.855 ccw(c122.37,162.169) 122.7,161.855 ; 122.7,161.855 ccw(c122.37,162.169) 122.701,161.856 ; 122.7,161.855 122.701,161.856 ; 122.7,161.855 122.701,161.856 ; 122.701,161.856 122.701,161.856 ; 122.701,161.856 ccw(c122.04,162.483) 122.701,161.856 ; 122.701,161.856 ccw(c122.04,162.483) 122.701,161.856 ; 122.701,161.856 122.861,162.024 ; 122.848,165.634 cw(c122.221,164.972) 122.848,165.633 ; 122.848,165.634 ccw(c122.221,164.972) 122.847,165.634 ; 122.848,165.634 122.848,165.633 ; 122.848,165.634 122.847,165.634 ; 122.847,165.634 cw(c122.534,165.303) 122.848,165.633 ; 122.848,165.633 cw(c122.534,165.303) 122.849,165.632 ; 122.848,165.633 ccw(c122.534,165.303) 122.848,165.633 ; 122.848,165.633 cw(c122.221,164.972) 122.849,165.632 ; 122.848,165.633 cw(c122.535,165.302) 122.849,165.633 cw(c122.221,164.972) 122.849,165.632 ; 122.848,165.633 122.849,165.632 ; 122.849,165.632 cw(c122.221,164.972) 122.966,165.498 ; 122.849,165.632 cw(c122.221,164.972) 122.966,165.498 ; 122.861,162.024 cw(c122.202,162.653) 122.86,162.024 ccw(c122.531,162.338) 122.861,162.024 ; 122.861,162.024 ccw(c122.202,162.653) 122.861,162.025 ; 122.861,162.025 ccw(c122.202,162.653) 122.862,162.025 ; 122.861,162.024 ccw(c122.531,162.338) 122.861,162.025 ; 122.861,162.025 ccw(c122.531,162.338) 122.862,162.025 ; 122.861,162.024 ccw(c122.531,162.338) 122.861,162.025 ; 122.861,162.024 ccw(c122.532,162.339) 122.861,162.025 ; 122.861,162.025 ccw(c122.532,162.339) 122.862,162.025 ; 122.861,162.025 122.862,162.025 ; 122.862,162.025 ccw(c122.202,162.653) 122.972,162.166 ; 122.862,162.025 ccw(c122.202,162.653) 122.862,162.025 ; 122.862,162.025 ccw(c122.202,162.653) 122.972,162.166 ; 122.966,165.498 123.101,165.306 ; 122.972,162.166 ccw(c122.202,162.653) 122.972,162.166 ; 122.972,162.166 ccw(c122.202,162.653) 122.972,162.167 ; 122.972,162.167 ccw(c122.202,162.653) 122.972,162.167 ; 122.972,162.167 ccw(c122.587,162.41) 122.972,162.167 ; 122.972,162.166 ccw(c122.587,162.41) 122.972,162.166 ; 122.972,162.166 ccw(c122.587,162.41) 122.972,162.167 ; 122.972,162.167 ccw(c122.587,162.41) 122.972,162.167 ; 122.972,162.166 ccw(c122.587,162.41) 122.972,162.166 ; 122.972,162.166 ccw(c122.587,162.41) 122.972,162.167 ; 122.972,162.167 ccw(c122.587,162.41) 122.972,162.167 ; 122.972,162.166 122.972,162.167 ; 122.972,162.167 ccw(c122.202,162.653) 122.973,162.168 cw(c122.587,162.41) 122.972,162.167 ; 122.972,162.167 123.097,162.364 ; 123.097,162.364 ccw(c122.328,162.852) 123.097,162.364 ; 123.097,162.364 ccw(c122.712,162.607) 123.097,162.364 ; 123.097,162.364 ccw(c122.713,162.608) 123.097,162.364 ; 123.097,162.364 ccw(c122.713,162.608) 123.097,162.364 ; 123.097,162.364 123.097,162.364 ; 123.097,162.364 ccw(c122.328,162.852) 123.178,162.524 ; 123.097,162.365 ccw(c122.328,162.852) 123.178,162.524 ; 123.097,162.364 ccw(c122.712,162.607) 123.097,162.364 ; 123.097,162.364 ccw(c122.713,162.608) 123.097,162.364 ; 123.097,162.364 ccw(c122.713,162.608) 123.097,162.365 ; 123.101,165.306 cw(c122.357,164.78) 123.189,165.151 ; 123.101,165.306 cw(c122.357,164.78) 123.189,165.151 ; 123.178,162.524 123.262,162.743 ; 123.19,165.149 ccw(c122.357,164.78) 123.19,165.15 ; 123.19,165.15 ccw(c122.357,164.78) 123.19,165.15 ; 123.19,165.15 ccw(c122.357,164.78) 123.189,165.151 ; 123.19,165.149 ccw(c122.774,164.965) 123.19,165.15 ; 123.19,165.15 ccw(c122.774,164.965) 123.19,165.15 ; 123.19,165.15 ccw(c122.773,164.965) 123.19,165.15 ; 123.19,165.15 ccw(c122.773,164.965) 123.19,165.15 ; 123.19,165.15 ccw(c122.774,164.965) 123.19,165.15 ; 123.19,165.15 ccw(c122.774,164.965) 123.189,165.151 ; 123.19,165.15 123.285,164.936 ; 123.19,165.15 123.189,165.151 ; 123.19,165.15 ccw(c122.357,164.78) 123.189,165.151 ; 123.262,162.743 ccw(c122.412,163.071) 123.31,162.915 ; 123.262,162.743 ccw(c122.412,163.071) 123.31,162.915 ; 123.285,164.935 cw(c122.453,164.565) 123.341,164.766 ; 123.285,164.935 ccw(c122.453,164.565) 123.285,164.936 ; 123.285,164.935 cw(c122.453,164.565) 123.341,164.766 ; 123.285,164.935 ccw(c122.453,164.565) 123.285,164.936 ; 123.285,164.936 ccw(c122.453,164.565) 123.285,164.936 ; 123.285,164.936 ccw(c122.869,164.75) 123.285,164.936 ; 123.285,164.936 ccw(c122.869,164.751) 123.285,164.936 ; 123.285,164.935 ccw(c122.869,164.751) 123.285,164.936 ; 123.285,164.936 ccw(c122.869,164.751) 123.285,164.936 ; 123.285,164.936 123.285,164.935 ; 123.285,164.936 ccw(c122.453,164.565) 123.285,164.937 ; 123.285,164.936 ccw(c122.869,164.751) 123.285,164.937 ; 123.31,162.915 ccw(c122.412,163.071) 123.31,162.915 ; 123.31,162.915 ccw(c122.412,163.071) 123.31,162.915 ; 123.31,162.915 ccw(c122.861,162.994) 123.31,162.915 ; 123.31,162.915 123.31,162.915 ; 123.31,162.915 ccw(c122.412,163.071) 123.31,162.915 ; 123.31,162.915 ccw(c122.412,163.071) 123.31,162.916 ; 123.31,162.915 ccw(c122.861,162.994) 123.31,162.917 ; 123.31,162.915 ccw(c122.861,162.993) 123.31,162.916 ; 123.31,162.915 ccw(c122.861,162.994) 123.31,162.916 ; 123.31,162.916 ccw(c122.412,163.071) 123.31,162.917 ; 123.31,162.916 123.31,162.916 ; 123.31,162.916 123.31,162.917 ; 123.31,162.917 ccw(c122.861,162.994) 123.31,162.917 ; 123.31,162.917 ccw(c122.861,162.994) 123.31,162.917 ; 123.31,162.917 123.35,163.146 ; 123.341,164.766 123.393,164.537 ; 123.35,163.146 ccw(c122.901,163.224) 123.35,163.146 ; 123.35,163.146 ccw(c122.901,163.224) 123.35,163.146 ; 123.35,163.146 ccw(c122.901,163.225) 123.35,163.146 ; 123.35,163.146 ccw(c122.901,163.225) 123.35,163.147 ; 123.35,163.146 ccw(c122.452,163.303) 123.35,163.146 ; 123.35,163.146 ccw(c122.452,163.303) 123.35,163.147 ; 123.35,163.146 123.35,163.146 ; 123.35,163.146 123.35,163.146 ; 123.35,163.146 123.35,163.147 ; 123.35,163.147 ccw(c122.901,163.225) 123.35,163.147 ; 123.35,163.147 ccw(c122.452,163.303) 123.361,163.237 ; 123.35,163.147 ccw(c122.452,163.303) 123.361,163.237 ; 123.35,163.146 ccw(c122.901,163.224) 123.35,163.147 ; 123.361,163.237 123.419,164.034 ; 123.393,164.537 cw(c122.505,164.336) 123.415,164.36 ; 123.393,164.537 cw(c122.505,164.336) 123.415,164.36 ; 123.415,164.36 ccw(c122.505,164.336) 123.415,164.36 ; 123.415,164.36 cw(c122.505,164.336) 123.415,164.359 ; 123.415,164.359 cw(c122.96,164.347) 123.415,164.359 ; 123.415,164.359 ccw(c122.96,164.347) 123.415,164.36 ; 123.415,164.359 cw(c122.96,164.348) 123.415,164.359 ; 123.415,164.359 ccw(c122.96,164.348) 123.415,164.36 ; 123.415,164.36 123.415,164.359 ; 123.415,164.358 ccw(c122.96,164.347) 123.415,164.359 ; 123.415,164.358 ccw(c122.505,164.336) 123.415,164.358 ; 123.415,164.358 ccw(c122.505,164.336) 123.415,164.359 ; 123.415,164.358 123.422,164.127 ; 123.415,164.358 123.415,164.358 ; 123.415,164.358 123.415,164.359 ; 123.415,164.359 ccw(c122.96,164.347) 123.415,164.359 ; 123.415,164.359 123.415,164.359 ; 123.419,164.034 ccw(c122.511,164.101) 123.422,164.125 ; 123.419,164.034 ccw(c122.511,164.101) 123.422,164.125 ; 123.422,164.125 ccw(c122.966,164.114) 123.422,164.125 ; 123.422,164.125 ccw(c122.966,164.114) 123.422,164.126 ; 123.422,164.125 ccw(c122.511,164.101) 123.422,164.126 ; 123.422,164.125 ccw(c122.966,164.113) 123.422,164.125 ; 123.422,164.125 ccw(c122.966,164.113) 123.422,164.126 ; 123.422,164.125 123.422,164.126 ; 123.422,164.126 ccw(c122.511,164.101) 123.422,164.127 ; 123.422,164.126 ccw(c122.966,164.114) 123.422,164.127 ; 123.422,164.126 123.422,164.126 ; 123.422,164.126 123.422,164.127 ; 123.422,164.127 123.422,164.127 ; 195.984,158.109 cw(c196.895,158.132) 195.997,158.287 ; 195.984,158.109 cw(c196.895,158.132) 195.997,158.287 ; 195.984,158.109 195.99,157.874 ; 195.99,157.874 ccw(c196.901,157.897) 196.012,157.696 ; 195.99,157.874 ccw(c196.901,157.897) 196.012,157.696 ; 195.997,158.287 196.037,158.518 ; 196.012,157.696 196.063,157.467 ; 196.037,158.518 cw(c196.935,158.363) 196.084,158.691 cw(c196.509,158.527) 196.084,158.691 ; 196.037,158.518 cw(c196.935,158.363) 196.084,158.691 ; 196.063,157.467 ccw(c196.952,157.667) 196.119,157.298 ; 196.063,157.467 ccw(c196.952,157.667) 196.119,157.298 ; 196.085,158.691 ccw(c196.935,158.363) 196.084,158.691 ; 196.085,158.692 ccw(c196.935,158.363) 196.085,158.691 ; 196.085,158.692 ccw(c196.935,158.363) 196.085,158.692 ; 196.084,158.691 ccw(c196.509,158.527) 196.084,158.691 ; 196.084,158.691 ccw(c196.51,158.528) 196.084,158.691 ; 196.085,158.692 ccw(c196.509,158.527) 196.084,158.691 ; 196.084,158.691 196.085,158.691 ; 196.084,158.691 196.085,158.692 ; 196.085,158.691 196.168,158.909 ; 196.119,157.298 196.215,157.083 ; 196.168,158.909 cw(c196.594,158.746) 196.169,158.91 ; 196.168,158.909 ccw(c197.019,158.583) 196.168,158.909 ; 196.168,158.909 ccw(c197.019,158.583) 196.168,158.909 ; 196.168,158.909 cw(c197.019,158.583) 196.169,158.91 ; 196.168,158.909 cw(c196.594,158.746) 196.169,158.91 ; 196.168,158.909 ccw(c196.594,158.746) 196.168,158.909 ; 196.168,158.909 196.169,158.91 ; 196.169,158.91 cw(c197.019,158.583) 196.249,159.069 ; 196.169,158.91 ccw(c196.594,158.746) 196.169,158.91 ; 196.169,158.91 cw(c197.019,158.583) 196.249,159.069 ; 196.215,157.083 ccw(c197.048,157.452) 196.303,156.927 ; 196.215,157.083 ccw(c197.048,157.452) 196.303,156.927 ; 196.249,159.069 196.374,159.268 ; 196.303,156.927 ccw(c196.675,157.19) 196.303,156.927 ; 196.303,156.927 ccw(c196.675,157.19) 196.303,156.927 ; 196.303,156.927 ccw(c196.675,157.19) 196.303,156.927 ; 196.303,156.927 ccw(c196.675,157.19) 196.303,156.927 ; 196.303,156.927 ccw(c197.048,157.452) 196.303,156.927 ; 196.303,156.927 ccw(c196.675,157.19) 196.303,156.927 ; 196.303,156.927 ccw(c197.048,157.452) 196.303,156.927 ; 196.303,156.927 ccw(c196.675,157.19) 196.303,156.927 ; 196.303,156.927 196.438,156.736 ; 196.303,156.927 196.303,156.927 ; 196.374,159.268 cw(c197.145,158.782) 196.484,159.409 ; 196.374,159.268 cw(c197.145,158.782) 196.484,159.409 ; 196.438,156.736 ccw(c197.183,157.26) 196.438,156.736 ; 196.438,156.736 ccw(c196.811,156.998) 196.438,156.736 ; 196.438,156.736 ccw(c196.811,156.998) 196.438,156.736 ; 196.438,156.736 ccw(c196.81,156.998) 196.438,156.736 ; 196.438,156.736 ccw(c196.811,156.998) 196.438,156.736 ; 196.437,156.736 ccw(c196.811,156.998) 196.438,156.736 ; 196.438,156.736 ccw(c196.81,156.998) 196.438,156.736 ; 196.437,156.736 ccw(c196.81,156.998) 196.438,156.736 ; 196.437,156.736 196.438,156.736 ; 196.438,156.735 ccw(c197.183,157.26) 196.555,156.6 ; 196.438,156.736 ccw(c196.811,156.998) 196.438,156.735 ; 196.438,156.736 ccw(c197.183,157.26) 196.555,156.6 ; 196.484,159.409 cw(c197.145,158.782) 196.484,159.409 ; 196.484,159.409 cw(c196.815,159.096) 196.484,159.409 ; 196.484,159.409 cw(c197.145,158.782) 196.484,159.41 ; 196.484,159.409 196.484,159.41 ; 196.484,159.41 ccw(c196.815,159.096) 196.484,159.409 ; 196.484,159.41 cw(c196.815,159.096) 196.485,159.411 ; 196.484,159.409 ccw(c196.814,159.095) 196.484,159.409 ; 196.484,159.41 cw(c196.815,159.096) 196.485,159.41 196.485,159.41 ; 196.484,159.41 ccw(c196.814,159.095) 196.484,159.409 ; 196.484,159.41 cw(c197.145,158.782) 196.485,159.41 ; 196.485,159.411 ccw(c197.145,158.782) 196.485,159.41 ; 196.485,159.41 196.485,159.411 ; 196.485,159.411 196.644,159.578 ; 196.556,156.599 ccw(c197.183,157.26) 196.556,156.599 ; 196.556,156.599 cw(c197.183,157.26) 196.555,156.6 ; 196.556,156.599 cw(c196.869,156.93) 196.555,156.6 ; 196.556,156.599 196.555,156.6 ; 196.555,156.6 ccw(c196.869,156.93) 196.555,156.6 ; 196.555,156.6 ccw(c196.87,156.929) 196.556,156.599 ; 196.555,156.6 ccw(c196.869,156.93) 196.555,156.6 ; 196.556,156.599 196.556,156.599 ; 196.555,156.6 196.556,156.599 ; 196.556,156.599 ccw(c197.183,157.26) 196.556,156.599 ; 196.556,156.599 196.724,156.439 ; 196.644,159.578 cw(c196.975,159.265) 196.645,159.579 ; 196.645,159.578 ccw(c197.306,158.952) 196.644,159.578 ; 196.645,159.578 cw(c197.306,158.952) 196.645,159.579 ; 196.645,159.578 196.645,159.579 ; 196.644,159.578 196.645,159.578 ; 196.645,159.579 ccw(c196.975,159.265) 196.645,159.579 ; 196.646,159.58 cw(c197.306,158.952) 196.781,159.696 ; 196.646,159.58 ccw(c196.975,159.265) 196.645,159.579 ; 196.646,159.58 ccw(c197.306,158.952) 196.645,159.579 ; 196.646,159.58 cw(c197.306,158.952) 196.781,159.696 ; 196.646,159.58 ccw(c196.976,159.266) 196.645,159.579 ; 196.646,159.58 ccw(c197.306,158.952) 196.646,159.58 ; 196.645,159.579 196.646,159.58 ; 196.724,156.439 ccw(c197.353,157.098) 196.725,156.439 ; 196.724,156.439 ccw(c197.038,156.769) 196.725,156.439 ; 196.725,156.439 ccw(c197.039,156.768) 196.725,156.438 ccw(c197.353,157.098) 196.725,156.438 ; 196.724,156.439 cw(c197.353,157.098) 196.724,156.44 ccw(c197.038,156.769) 196.724,156.439 ; 196.724,156.439 ccw(c197.039,156.768) 196.725,156.439 ; 196.724,156.439 ccw(c197.038,156.769) 196.725,156.439 ; 196.725,156.439 ccw(c197.353,157.098) 196.725,156.438 ; 196.725,156.439 ccw(c197.038,156.769) 196.725,156.438 ; 196.725,156.439 196.725,156.438 ; 196.725,156.438 ccw(c197.353,157.098) 196.866,156.328 ; 196.725,156.438 ccw(c197.353,157.098) 196.866,156.328 ; 196.781,159.696 196.973,159.832 ; 196.866,156.328 ccw(c197.11,156.713) 196.866,156.328 ; 196.866,156.328 ccw(c197.353,157.098) 196.867,156.328 ; 196.866,156.328 ccw(c197.353,157.098) 196.866,156.328 ; 196.866,156.328 196.867,156.328 ; 196.867,156.328 ccw(c197.353,157.098) 196.868,156.327 cw(c197.11,156.713) 196.867,156.328 ; 196.867,156.328 ccw(c197.11,156.713) 196.867,156.328 ; 196.867,156.328 ccw(c197.353,157.098) 196.867,156.328 ; 196.867,156.328 ccw(c197.11,156.713) 196.867,156.328 ; 196.866,156.328 ccw(c197.11,156.713) 196.867,156.328 ; 196.866,156.328 ccw(c197.11,156.713) 196.866,156.328 ; 196.867,156.328 ccw(c197.11,156.713) 196.867,156.328 ; 196.866,156.328 ccw(c197.11,156.713) 196.867,156.328 ; 196.867,156.328 197.064,156.203 ; 196.973,159.832 cw(c197.499,159.088) 197.128,159.92 ; 196.973,159.832 cw(c197.499,159.088) 197.128,159.92 ; 197.063,156.204 ccw(c197.552,156.972) 197.064,156.203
